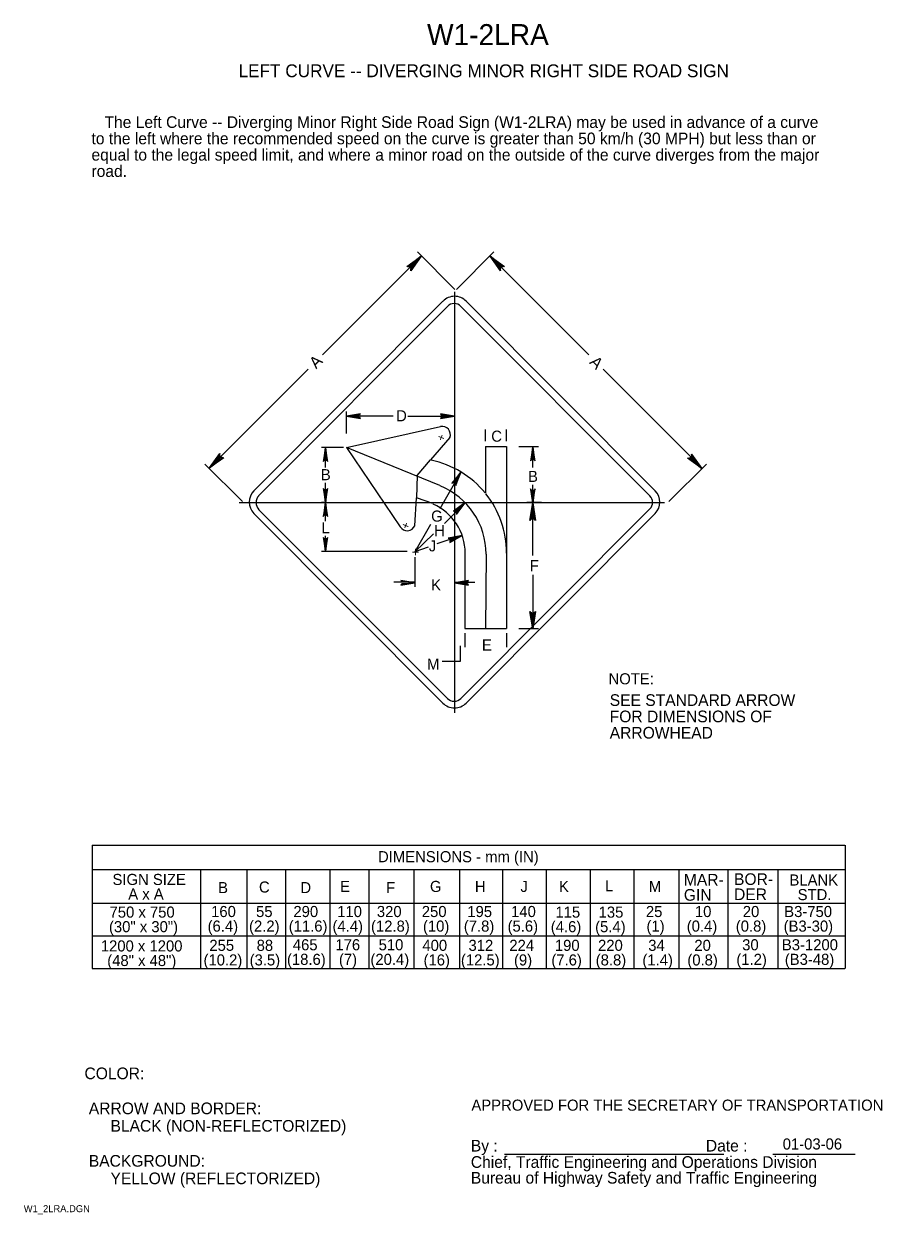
# Model space of a CAD drawing. Extents: x 0.013 to 0.196, y 0.004 to 0.259.
import ezdxf

# ---------------------------------------------------------------- set-up
doc = ezdxf.new("R2010")
doc.units = 0
for name, color, linetype in [('1', 7, 'Continuous'), ('2', 7, 'Continuous'), ('3', 7, 'Continuous'), ('4', 7, 'Continuous')]:
    doc.layers.add(name, color=color, linetype=linetype)

# ---------------------------------------------------------------- blocks, each defined once
blk = doc.blocks.new('RARROW')
at = {"layer": '3'}
for p, q in [((-2.156, 0.28500000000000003), (-2.2665, 0.384625)), ((-2.2665, 0.384625), (0, 0)), ((0, 0), (-2.2665, -0.379125)), ((-2.156, 0.28500000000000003), (-2.075625, 0.12075)), ((0, 0), (-2.156, 0.28500000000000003)), ((-2.14975, -0.2705), (0, 0)), ((-2.075625, 0.12075), (0, 0)), ((0, 0), (-2.074, -0.108)), ((-2.2665, -0.379125), (-2.14975, -0.2705)), ((-2.074, -0.108), (-2.14975, -0.2705))]:
    blk.add_line(p, q, dxfattribs=at)

msp = doc.modelspace()

# ---------------------------------------------------------------- linework, layer by layer
at = {"layer": '1'}
for p, q in [((0.11543984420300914, 0.01682017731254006), (0.16244318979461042, 0.01682017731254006)), ((0.17295324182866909, 0.01682017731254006), (0.19056484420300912, 0.01682017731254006))]:
    msp.add_line(p, q, dxfattribs=at)
at = {"layer": '3'}
for p, q in [((0.07649568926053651, 0.18811790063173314), (0.09768889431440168, 0.2093111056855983)), ((0.10484834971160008, 0.2021516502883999), (0.09680500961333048, 0.2101949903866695)), ((0.10515165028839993, 0.2021516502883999), (0.11319499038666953, 0.2101949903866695)), ((0.13350431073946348, 0.18811790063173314), (0.11231110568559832, 0.2093111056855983)), ((0.10475, 0.201625), (0.10475, 0.111375)), ((0.06175, 0.159), (0.10225000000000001, 0.199625)), ((0.10725, 0.199625), (0.14775, 0.159)), ((0.06275, 0.15787500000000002), (0.10325000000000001, 0.1985)), ((0.106125, 0.1985), (0.146625, 0.15787500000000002)), ((0.073402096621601, 0.18502431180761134), (0.052188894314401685, 0.1638111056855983)), ((0.136597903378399, 0.18502431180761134), (0.1578111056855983, 0.1638111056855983)), ((0.081625, 0.17125), (0.081625, 0.176)), ((0.091625, 0.17500000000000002), (0.081625, 0.17500000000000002)), ((0.09475, 0.17500000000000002), (0.10475, 0.17500000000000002)), ((0.10475, 0.17525000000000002), (0.10475, 0.17400000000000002)), ((0.081625, 0.16825), (0.10175000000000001, 0.17275000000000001)), ((0.111375, 0.169625), (0.111375, 0.172125)), ((0.115875, 0.169625), (0.115875, 0.172125)), ((0.10375000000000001, 0.170375), (0.099625, 0.165625)), ((0.111375, 0.1685), (0.115875, 0.1685)), ((0.111375, 0.1685), (0.111375, 0.1585)), ((0.115875, 0.1685), (0.115875, 0.1295)), ((0.11850000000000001, 0.1685), (0.12275, 0.1685)), ((0.12154158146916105, 0.16399713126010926), (0.12154158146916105, 0.16849713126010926)), ((0.081, 0.16825), (0.07625, 0.16825)), ((0.077125, 0.164), (0.077125, 0.16825)), ((0.10162500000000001, 0.160125), (0.081625, 0.16825)), ((0.081625, 0.16825), (0.093125, 0.15125)), ((0.059348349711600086, 0.15665165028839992), (0.05130500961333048, 0.16469499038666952)), ((0.09675, 0.16225), (0.099625, 0.165625)), ((0.1506516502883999, 0.15665165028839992), (0.1586949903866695, 0.16469499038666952)), ((0.09675, 0.16225), (0.096625, 0.1575)), ((0.106125, 0.163), (0.10162500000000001, 0.155125)), ((0.077125, 0.1565), (0.077125, 0.16072275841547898)), ((0.12154158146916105, 0.15149713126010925), (0.12154158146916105, 0.16024090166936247)), ((0.058625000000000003, 0.1565), (0.14975, 0.1565)), ((0.077375, 0.1565), (0.07625, 0.1565)), ((0.077125, 0.1525), (0.077125, 0.1565)), ((0.09625, 0.1515), (0.096625, 0.1575)), ((0.100125, 0.15625), (0.096625, 0.1575)), ((0.107, 0.15637500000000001), (0.10262500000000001, 0.152)), ((0.123375, 0.1565), (0.12025, 0.1565)), ((0.1215, 0.145125), (0.1215, 0.1565)), ((0.10225000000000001, 0.1135), (0.06175, 0.154125)), ((0.10325000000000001, 0.1145), (0.06275, 0.155)), ((0.146625, 0.155125), (0.106125, 0.1145)), ((0.14775, 0.154125), (0.10725, 0.1135)), ((0.099625, 0.15175), (0.09625, 0.145875)), ((0.077125, 0.146), (0.077125, 0.14936379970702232)), ((0.10025, 0.14975), (0.09625, 0.145875)), ((0.106375, 0.149375), (0.101, 0.147625)), ((0.094625, 0.146), (0.07625, 0.146)), ((0.099125, 0.146875), (0.09625, 0.145875)), ((0.107, 0.145625), (0.107, 0.1295)), ((0.09625, 0.14475), (0.09625, 0.138375)), ((0.1115, 0.145375), (0.111375, 0.1295)), ((0.1215, 0.14100000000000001), (0.1215, 0.1295)), ((0.09625, 0.139375), (0.09175, 0.139375)), ((0.10475, 0.140125), (0.10475, 0.138375)), ((0.10475, 0.139375), (0.109125, 0.139375)), ((0.107, 0.1295), (0.115875, 0.1295)), ((0.107, 0.1285), (0.107, 0.1255)), ((0.115875, 0.1285), (0.115875, 0.1255)), ((0.11850000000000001, 0.1295), (0.12275, 0.1295)), ((0.027125, 0.083), (0.18837500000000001, 0.083)), ((0.027166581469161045, 0.08299713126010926), (0.027166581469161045, 0.05662213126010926)), ((0.18841658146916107, 0.08299713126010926), (0.18841658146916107, 0.05662213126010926)), ((0.18837500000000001, 0.07775), (0.027125, 0.07775)), ((0.050381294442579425, 0.07774713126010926), (0.050381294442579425, 0.05662213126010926)), ((0.06029158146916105, 0.07774713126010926), (0.06029158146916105, 0.05662213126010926)), ((0.06854158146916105, 0.07774713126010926), (0.06854158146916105, 0.05662213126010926)), ((0.07804158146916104, 0.07774713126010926), (0.07804158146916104, 0.05662213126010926)), ((0.08641658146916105, 0.07774713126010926), (0.08641658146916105, 0.05662213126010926)), ((0.09604158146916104, 0.07774713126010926), (0.09604158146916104, 0.05662213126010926)), ((0.10579158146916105, 0.07774713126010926), (0.10579158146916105, 0.05662213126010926)), ((0.11504158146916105, 0.07774713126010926), (0.11504158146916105, 0.05662213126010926)), ((0.12441658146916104, 0.07774713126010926), (0.12441658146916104, 0.05662213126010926)), ((0.13379158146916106, 0.07774713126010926), (0.13379158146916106, 0.05662213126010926)), ((0.14316658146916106, 0.07774713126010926), (0.14316658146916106, 0.05662213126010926)), ((0.15281657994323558, 0.07774713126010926), (0.15281657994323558, 0.05662213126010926)), ((0.16329158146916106, 0.07774713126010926), (0.16329158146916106, 0.05662213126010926)), ((0.17404158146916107, 0.07774713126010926), (0.17404158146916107, 0.05662213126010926)), ((0.027125, 0.07062500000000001), (0.18837500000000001, 0.07062500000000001)), ((0.027125, 0.063625), (0.18837500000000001, 0.063625)), ((0.027125, 0.056625), (0.18837500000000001, 0.056625))]:
    msp.add_line(p, q, dxfattribs=at)
msp.add_lwpolyline([(0.106, 0.12575), (0.106, 0.122375), (0.10212500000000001, 0.122375)], dxfattribs=at)
for centre, radius, start, end in [((0.104772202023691, 0.19718425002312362), 0.0034780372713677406, 44.56843888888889, 135.49785833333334), ((0.1046875, 0.19708563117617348), 0.0020166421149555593, 44.535291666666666, 135.46471111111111), ((0.10212832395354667, 0.17102622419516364), 0.0017475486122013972, 338.12085, 102.38894166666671), ((0.09562520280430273, 0.14564873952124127), 0.0203, 39.47509166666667, 78.2019277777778), ((0.06426195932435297, 0.15655963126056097), 0.003470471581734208, 135.38381666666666, 224.61618055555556), ((0.09575020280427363, 0.14539873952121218), 0.0157686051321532, 0, 67.97055), ((0.09562520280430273, 0.14564873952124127), 0.0203, 0, 38.760247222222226), ((0.14526897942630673, 0.1565624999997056), 0.0034780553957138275, 315.50695833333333, 44.49304444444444), ((0.06433263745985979, 0.15646106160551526), 0.0020894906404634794, 135.70475555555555, 224.93711944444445), ((0.09562520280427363, 0.14564873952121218), 0.01141875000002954, 0, 66.27881944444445), ((0.145225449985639, 0.15650000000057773), 0.0019619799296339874, 315.5069555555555, 44.49304166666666), ((0.09462141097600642, 0.15220111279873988), 0.001773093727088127, 212.439875, 336.70796666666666), ((0.10474999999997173, 0.11589162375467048), 0.003459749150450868, 223.73079444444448, 316.2692083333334), ((0.1046875, 0.11587518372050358), 0.0019893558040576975, 223.73079444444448, 316.2692083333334)]:
    msp.add_arc(centre, radius, start, end, dxfattribs=at)

# ---------------------------------------------------------------- block references
for p, xscale, yscale, rotation in [((0.097625, 0.20925), 0.0016545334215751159, 0.0016366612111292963, 44.999999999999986), ((0.112375, 0.20925), 0.0016545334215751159, 0.0016366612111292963, 135.00000000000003), ((0.081625, 0.17500000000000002), 0.0013236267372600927, -0.001309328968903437, 180), ((0.05225, 0.163875), 0.001654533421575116, 0.001636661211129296, -135), ((0.077125, 0.16825), 0.0013236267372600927, -0.001309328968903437, 90), ((0.1215, 0.168375), 0.0013236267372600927, -0.001309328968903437, 90), ((0.15775, 0.16375), 0.0016545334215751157, 0.001636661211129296, -45), ((0.106125, 0.163), 0.0013236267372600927, -0.0013093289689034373, 60.16446089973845), ((0.077125, 0.1565), 0.0013236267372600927, -0.001309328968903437, -90), ((0.1215, 0.15637500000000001), 0.0013236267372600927, -0.001309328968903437, -90), ((0.077125, 0.1565), 0.0013236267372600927, -0.001309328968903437, 90), ((0.107, 0.15637500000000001), 0.0013236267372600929, -0.001309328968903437, 44.3259631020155), ((0.1215, 0.15637500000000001), 0.0016545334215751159, 0.0016366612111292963, 90), ((0.077125, 0.146), 0.0013236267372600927, -0.001309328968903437, -90), ((0.106375, 0.149375), 0.0013236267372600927, -0.0013093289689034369, 19.698621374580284), ((0.10475, 0.13925), 0.0013236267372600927, -0.001309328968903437, 180), ((0.1215, 0.129375), 0.0016545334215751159, 0.0016366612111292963, -90)]:
    msp.add_blockref('RARROW', p, dxfattribs=dict(at, xscale=xscale, yscale=yscale, rotation=rotation))
at = {"layer": '3', "xscale": 0.0013236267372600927, "yscale": -0.001309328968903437}
for p in [(0.10475, 0.17500000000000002), (0.09625, 0.13925)]:
    msp.add_blockref('RARROW', p, dxfattribs=at)

# ---------------------------------------------------------------- texts
at = {"layer": '1'}
for s, height, p in [('W1-2LRA', 0.0045000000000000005, (0.098875, 0.2545)), ('LEFT CURVE -- DIVERGING MINOR RIGHT SIDE ROAD SIGN', 0.00275025, (0.0585, 0.247625)), ('G', 0.0023752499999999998, (0.09975, 0.152375)), ('H', 0.0023752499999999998, (0.100375, 0.14925)), ('J', 0.0023752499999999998, (0.09925, 0.146)), ('NOTE:', 0.0023752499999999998, (0.13775, 0.11750000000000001)), ('SEE STANDARD ARROW', 0.0024997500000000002, (0.138, 0.112875)), ('FOR DIMENSIONS OF', 0.0024997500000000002, (0.138, 0.109375)), ('ARROWHEAD', 0.0024997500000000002, (0.138, 0.105875)), ('COLOR:', 0.0024997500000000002, (0.025500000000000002, 0.032875)), ('APPROVED FOR THE SECRETARY OF TRANSPORTATION', 0.0023752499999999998, (0.108375, 0.026125)), (' ARROW AND BORDER:', 0.0024997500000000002, (0.025500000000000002, 0.025375)), ('      BLACK (NON-REFLECTORIZED)', 0.0024997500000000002, (0.025500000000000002, 0.021625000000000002)), ('By :                                                Date :', 0.0024997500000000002, (0.10825, 0.017375)), (' BACKGROUND:', 0.0024997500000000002, (0.025500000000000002, 0.014125)), ('Chief, Traffic Engineering and Operations Division', 0.0024997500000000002, (0.10825, 0.013875)), ('      YELLOW (REFLECTORIZED)', 0.0024997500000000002, (0.025500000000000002, 0.010375)), ('Bureau of Highway Safety and Traffic Engineering', 0.0024997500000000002, (0.10825, 0.0105)), ('W1_2LRA.DGN', 0.0015, (0.0125, 0.004375))]:
    msp.add_text(s, height=height, dxfattribs=at).set_placement(p)
at = {"layer": '2'}
for s, p in [('   The Left Curve -- Diverging Minor Right Side Road Sign (W1-2LRA) may be used in advance of a curve', (0.027, 0.23675000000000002)), ('to the left where the recommended speed on the curve is greater than 50 km/h (30 MPH) but less than or', (0.027, 0.23325)), ('equal to the legal speed limit, and where a minor road on the outside of the curve diverges from the major', (0.027, 0.22975)), ('road.', (0.027, 0.22625))]:
    msp.add_text(s, height=0.0024997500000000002, dxfattribs=at).set_placement(p)
at = {"layer": '3'}
for s, height, rotation, p in [('A', 0.0024997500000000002, 45, (0.075125, 0.185)), ('A', 0.0024997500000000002, 315, (0.1335, 0.186375)), ('+', 0.0017775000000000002, 248.12085000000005, (0.101375, 0.171375)), ('+', 0.0017775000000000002, 248.12085000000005, (0.09375, 0.1525))]:
    msp.add_text(s, height=height, rotation=rotation, dxfattribs=at).set_placement(p)
for s, height, p in [('D', 0.0023752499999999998, (0.09225, 0.173875)), ('C', 0.0023752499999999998, (0.112625, 0.1695)), ('B', 0.0023752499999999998, (0.076125, 0.16125)), ('B', 0.0023752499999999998, (0.1205, 0.160875)), ('L', 0.0023752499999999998, (0.07625, 0.149875)), ('+', 0.00200025, (0.095625, 0.144875)), ('F', 0.0023752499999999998, (0.120875, 0.14175000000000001)), ('K', 0.0023752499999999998, (0.09975, 0.137625)), ('E', 0.0023752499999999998, (0.110625, 0.12475)), ('M', 0.0023752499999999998, (0.098875, 0.120625)), ('DIMENSIONS - mm (IN)', 0.0023752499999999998, (0.088375, 0.079375)), ('SIGN SIZE', 0.0023752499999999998, (0.0315, 0.0745)), ('MAR-', 0.0024997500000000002, (0.153875, 0.074375)), ('BOR-', 0.0024997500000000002, (0.164625, 0.0745)), ('BLANK', 0.0023752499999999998, (0.1765, 0.074375)), ('B', 0.0023752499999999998, (0.054125, 0.07275)), ('C', 0.0023752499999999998, (0.062875, 0.072875)), ('D', 0.0023752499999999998, (0.07175000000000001, 0.07275)), ('E', 0.0023752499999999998, (0.08025, 0.073)), ('F', 0.0023752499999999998, (0.090125, 0.07275)), ('G', 0.0023752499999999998, (0.0995, 0.073)), ('H', 0.0023752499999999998, (0.109125, 0.073)), ('J', 0.0023752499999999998, (0.11887500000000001, 0.073)), ('K', 0.0023752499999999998, (0.12712500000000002, 0.073)), ('L', 0.0023752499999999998, (0.137, 0.073125)), ('M', 0.0023752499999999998, (0.146375, 0.073)), ('A x A', 0.0023752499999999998, (0.034875, 0.07137500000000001)), ('GIN', 0.0024997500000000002, (0.153875, 0.07112500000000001)), ('DER', 0.0024997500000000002, (0.164625, 0.07125000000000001)), ('STD.', 0.0023752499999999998, (0.17825, 0.07125000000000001)), ('750 x 750', 0.0023752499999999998, (0.030875, 0.0675)), ('160', 0.0023752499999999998, (0.052625, 0.067625)), ('55', 0.0023752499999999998, (0.06225, 0.067625)), ('290', 0.0023752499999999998, (0.07025, 0.067625)), ('110', 0.0023752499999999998, (0.079625, 0.067625)), ('320', 0.0023752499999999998, (0.088125, 0.067625)), ('250', 0.0023752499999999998, (0.09775, 0.067625)), ('195', 0.0023752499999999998, (0.1075, 0.067625)), ('140', 0.0023752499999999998, (0.116875, 0.067625)), ('115', 0.0023752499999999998, (0.12637500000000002, 0.0675)), ('135', 0.0023752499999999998, (0.135625, 0.0675)), ('25', 0.0023752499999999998, (0.14575, 0.067625)), ('10', 0.0023752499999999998, (0.15625, 0.067625)), ('20', 0.0023752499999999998, (0.1665, 0.067625)), ('B3-750', 0.0023752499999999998, (0.175375, 0.067625)), ('(30" x 30")', 0.0023752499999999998, (0.03075, 0.064375)), ('(6.4)', 0.0023752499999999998, (0.051875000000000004, 0.0645)), ('(2.2)', 0.0023752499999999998, (0.06075, 0.0645)), ('(11.6)', 0.0023752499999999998, (0.06925, 0.0645)), ('(4.4)', 0.0023752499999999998, (0.078625, 0.0645)), ('(12.8)', 0.0023752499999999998, (0.08687500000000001, 0.0645)), ('(10)', 0.0023752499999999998, (0.098, 0.0645)), ('(7.8)', 0.0023752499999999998, (0.10675, 0.0645)), ('(5.6)', 0.0023752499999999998, (0.116125, 0.0645)), ('(4.6)', 0.0023752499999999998, (0.12537500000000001, 0.064375)), ('(5.4)', 0.0023752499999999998, (0.134875, 0.064375)), ('(1)', 0.0023752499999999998, (0.145875, 0.0645)), ('(0.4)', 0.0023752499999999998, (0.1545, 0.0645)), ('(0.8)', 0.0023752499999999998, (0.165, 0.0645)), ('(B3-30)', 0.0023752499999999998, (0.17525000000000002, 0.0645)), ('1200 x 1200', 0.0023752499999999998, (0.029, 0.06025)), ('255', 0.0023752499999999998, (0.05225, 0.060375)), ('88', 0.0023752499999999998, (0.062375, 0.060375)), ('465', 0.0023752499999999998, (0.070125, 0.0605)), ('176', 0.0023752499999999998, (0.07925, 0.0605)), ('510', 0.0023752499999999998, (0.0885, 0.0605)), ('400', 0.0023752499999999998, (0.097875, 0.060375)), ('312', 0.0023752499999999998, (0.10775, 0.060375)), ('224', 0.0023752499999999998, (0.1165, 0.060375)), ('190', 0.0023752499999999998, (0.12625, 0.060375)), ('220', 0.0023752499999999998, (0.1355, 0.060375)), ('34', 0.0023752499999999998, (0.14625, 0.060375)), ('20', 0.0023752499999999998, (0.156125, 0.060375)), ('30', 0.0023752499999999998, (0.166375, 0.0605)), ('B3-1200', 0.0023752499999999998, (0.174875, 0.0605)), ('(48" x 48")', 0.0023752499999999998, (0.030375, 0.057125)), ('(10.2)', 0.0023752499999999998, (0.051000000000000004, 0.05725)), ('(3.5)', 0.0023752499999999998, (0.060875, 0.05725)), ('(18.6)', 0.0023752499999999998, (0.068875, 0.057375)), ('(7)', 0.0023752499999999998, (0.08, 0.057375)), ('(20.4)', 0.0023752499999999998, (0.08675000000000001, 0.057375)), ('(16)', 0.0023752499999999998, (0.098125, 0.05725)), ('(12.5)', 0.0023752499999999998, (0.106125, 0.05725)), ('(9)', 0.0023752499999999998, (0.11750000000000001, 0.05725)), ('(7.6)', 0.0023752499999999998, (0.1255, 0.05725)), ('(8.8)', 0.0023752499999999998, (0.135, 0.05725)), ('(1.4)', 0.0023752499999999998, (0.145, 0.05725)), ('(0.8)', 0.0023752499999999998, (0.154625, 0.05725)), ('(1.2)', 0.0023752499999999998, (0.165125, 0.057375)), ('(B3-48)', 0.0023752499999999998, (0.17550000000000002, 0.057375))]:
    msp.add_text(s, height=height, dxfattribs=at).set_placement(p)
at = {"layer": '4'}
msp.add_text('01-03-06', height=0.0023752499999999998, dxfattribs=at).set_placement((0.17505242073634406, 0.01780528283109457))

doc.saveas('drawing.dxf')
